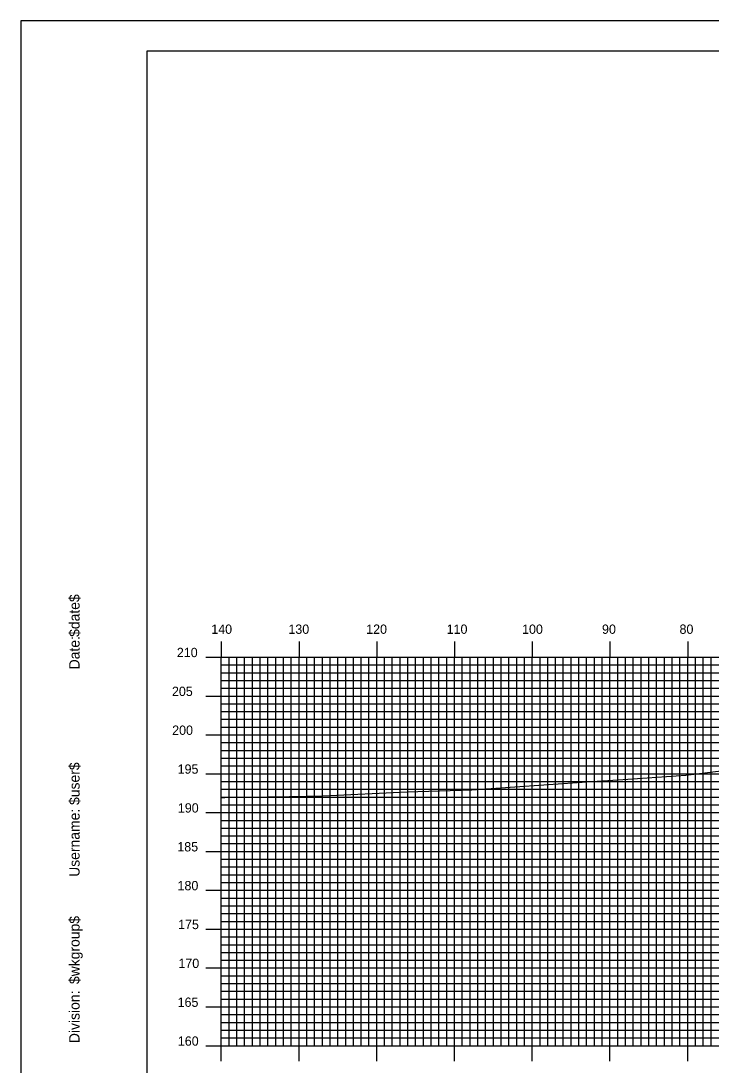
# Model space of a CAD drawing. Extents: x 1794846 to 1795189, y 442591 to 442811.
# Drawn here: x 1794846.1 to 1794934.9, y 442676.2 to 442810.5 of the extents above; entities that cross this region are included whole.
import ezdxf

# ---------------------------------------------------------------- set-up
doc = ezdxf.new("R2010")
doc.units = 0
for name, color, linetype in [('BORDER', 7, 'Continuous'), ('H_V ANNOTATION', 7, 'Continuous'), ('MAJOR', 7, 'Continuous'), ('MINOR', 7, 'Continuous'), ('PLOT BOUNDARY', 7, 'Continuous'), ('S_Roadway_Centerline', 7, 'Continuous')]:
    doc.layers.add(name, color=color, linetype=linetype)

msp = doc.modelspace()

# ---------------------------------------------------------------- linework, layer by layer
at = {"layer": 'BORDER'}
msp.add_lwpolyline([(1794862.25, 442596.67), (1795182.25, 442596.67), (1795182.25, 442806.67), (1794862.25, 442806.67)], close=True, dxfattribs=at)
at = {"layer": 'MAJOR'}
for p, q in [((1794871.85, 442730.67), (1794871.85, 442728.67)), ((1794881.85, 442730.67), (1794881.85, 442728.67)), ((1794891.85, 442730.67), (1794891.85, 442728.67)), ((1794901.85, 442730.67), (1794901.85, 442728.67)), ((1794911.85, 442730.67), (1794911.85, 442728.67)), ((1794921.85, 442730.67), (1794921.85, 442728.67)), ((1794931.85, 442730.67), (1794931.85, 442728.67)), ((1794869.85, 442728.67), (1794871.85, 442728.67)), ((1794871.85, 442728.67), (1795151.85, 442728.67)), ((1794871.85, 442678.67), (1794871.85, 442728.67)), ((1794871.85, 442678.67), (1794871.85, 442728.67)), ((1794871.85, 442728.67), (1795151.85, 442728.67)), ((1794881.85, 442678.67), (1794881.85, 442728.67)), ((1794891.85, 442678.67), (1794891.85, 442728.67)), ((1794901.85, 442678.67), (1794901.85, 442728.67)), ((1794911.85, 442678.67), (1794911.85, 442728.67)), ((1794921.85, 442678.67), (1794921.85, 442728.67)), ((1794931.85, 442678.67), (1794931.85, 442728.67)), ((1794869.85, 442723.67), (1794871.85, 442723.67)), ((1794871.85, 442723.67), (1795151.85, 442723.67)), ((1794869.85, 442718.67), (1794871.85, 442718.67)), ((1794871.85, 442718.67), (1795151.85, 442718.67)), ((1794869.85, 442713.67), (1794871.85, 442713.67)), ((1794871.85, 442713.67), (1795151.85, 442713.67)), ((1794869.85, 442708.67), (1794871.85, 442708.67)), ((1794871.85, 442708.67), (1795151.85, 442708.67)), ((1794869.85, 442703.67), (1794871.85, 442703.67)), ((1794871.85, 442703.67), (1795151.85, 442703.67)), ((1794869.85, 442698.67), (1794871.85, 442698.67)), ((1794871.85, 442698.67), (1795151.85, 442698.67)), ((1794869.85, 442693.67), (1794871.85, 442693.67)), ((1794871.85, 442693.67), (1795151.85, 442693.67)), ((1794869.85, 442688.67), (1794871.85, 442688.67)), ((1794871.85, 442688.67), (1795151.85, 442688.67)), ((1794869.85, 442683.67), (1794871.85, 442683.67)), ((1794871.85, 442683.67), (1795151.85, 442683.67)), ((1794869.85, 442678.67), (1794871.85, 442678.67)), ((1794871.85, 442678.67), (1795151.85, 442678.67)), ((1794871.85, 442678.67), (1795151.85, 442678.67)), ((1794871.85, 442676.66), (1794871.85, 442678.67)), ((1794881.85, 442676.66), (1794881.85, 442678.67)), ((1794891.85, 442676.66), (1794891.85, 442678.67)), ((1794901.85, 442676.66), (1794901.85, 442678.67)), ((1794911.85, 442676.66), (1794911.85, 442678.67)), ((1794921.85, 442676.66), (1794921.85, 442678.67)), ((1794931.85, 442676.66), (1794931.85, 442678.67))]:
    msp.add_line(p, q, dxfattribs=at)
at = {"layer": 'MINOR'}
for p, q in [((1794872.85, 442678.67), (1794872.85, 442728.67)), ((1794873.85, 442678.67), (1794873.85, 442728.67)), ((1794874.85, 442678.67), (1794874.85, 442728.67)), ((1794875.85, 442678.67), (1794875.85, 442728.67)), ((1794876.85, 442678.67), (1794876.85, 442728.67)), ((1794877.85, 442678.67), (1794877.85, 442728.67)), ((1794878.85, 442678.67), (1794878.85, 442728.67)), ((1794879.85, 442678.67), (1794879.85, 442728.67)), ((1794880.85, 442678.67), (1794880.85, 442728.67)), ((1794882.85, 442678.67), (1794882.85, 442728.67)), ((1794883.85, 442678.67), (1794883.85, 442728.67)), ((1794884.85, 442678.67), (1794884.85, 442728.67)), ((1794885.85, 442678.67), (1794885.85, 442728.67)), ((1794886.85, 442678.67), (1794886.85, 442728.67)), ((1794887.85, 442678.67), (1794887.85, 442728.67)), ((1794888.85, 442678.67), (1794888.85, 442728.67)), ((1794889.85, 442678.67), (1794889.85, 442728.67)), ((1794890.85, 442678.67), (1794890.85, 442728.67)), ((1794892.85, 442678.67), (1794892.85, 442728.67)), ((1794893.85, 442678.67), (1794893.85, 442728.67)), ((1794894.85, 442678.67), (1794894.85, 442728.67)), ((1794895.85, 442678.67), (1794895.85, 442728.67)), ((1794896.85, 442678.67), (1794896.85, 442728.67)), ((1794897.85, 442678.67), (1794897.85, 442728.67)), ((1794898.85, 442678.67), (1794898.85, 442728.67)), ((1794899.85, 442678.67), (1794899.85, 442728.67)), ((1794900.85, 442678.67), (1794900.85, 442728.67)), ((1794902.85, 442678.67), (1794902.85, 442728.67)), ((1794903.85, 442678.67), (1794903.85, 442728.67)), ((1794904.85, 442678.67), (1794904.85, 442728.67)), ((1794905.85, 442678.67), (1794905.85, 442728.67)), ((1794906.85, 442678.67), (1794906.85, 442728.67)), ((1794907.85, 442678.67), (1794907.85, 442728.67)), ((1794908.85, 442678.67), (1794908.85, 442728.67)), ((1794909.85, 442678.67), (1794909.85, 442728.67)), ((1794910.85, 442678.67), (1794910.85, 442728.67)), ((1794912.85, 442678.67), (1794912.85, 442728.67)), ((1794913.85, 442678.67), (1794913.85, 442728.67)), ((1794914.85, 442678.67), (1794914.85, 442728.67)), ((1794915.85, 442678.67), (1794915.85, 442728.67)), ((1794916.85, 442678.67), (1794916.85, 442728.67)), ((1794917.85, 442678.67), (1794917.85, 442728.67)), ((1794918.85, 442678.67), (1794918.85, 442728.67)), ((1794919.85, 442678.67), (1794919.85, 442728.67)), ((1794920.85, 442678.67), (1794920.85, 442728.67)), ((1794922.85, 442678.67), (1794922.85, 442728.67)), ((1794923.85, 442678.67), (1794923.85, 442728.67)), ((1794924.85, 442678.67), (1794924.85, 442728.67)), ((1794925.85, 442678.67), (1794925.85, 442728.67)), ((1794926.85, 442678.67), (1794926.85, 442728.67)), ((1794927.85, 442678.67), (1794927.85, 442728.67)), ((1794928.85, 442678.67), (1794928.85, 442728.67)), ((1794929.85, 442678.67), (1794929.85, 442728.67)), ((1794930.85, 442678.67), (1794930.85, 442728.67)), ((1794932.85, 442678.67), (1794932.85, 442728.67)), ((1794933.85, 442678.67), (1794933.85, 442728.67)), ((1794934.85, 442678.67), (1794934.85, 442728.67)), ((1794871.85, 442727.67), (1795151.85, 442727.67)), ((1794871.85, 442727.67), (1794873.86, 442727.67)), ((1794871.85, 442726.67), (1795151.85, 442726.67)), ((1794871.85, 442726.67), (1794873.86, 442726.67)), ((1794871.85, 442725.67), (1795151.85, 442725.67)), ((1794871.85, 442725.67), (1794873.86, 442725.67)), ((1794871.85, 442724.67), (1795151.85, 442724.67)), ((1794871.85, 442724.67), (1794873.86, 442724.67)), ((1794871.85, 442722.67), (1795151.85, 442722.67)), ((1794871.85, 442722.67), (1794873.86, 442722.67)), ((1794871.85, 442721.67), (1795151.85, 442721.67)), ((1794871.85, 442721.67), (1794873.86, 442721.67)), ((1794871.85, 442720.67), (1795151.85, 442720.67)), ((1794871.85, 442720.67), (1794873.86, 442720.67)), ((1794871.85, 442719.67), (1795151.85, 442719.67)), ((1794871.85, 442719.67), (1794873.86, 442719.67)), ((1794871.85, 442717.67), (1795151.85, 442717.67)), ((1794871.85, 442717.67), (1794873.86, 442717.67)), ((1794871.85, 442716.67), (1795151.85, 442716.67)), ((1794871.85, 442716.67), (1794873.86, 442716.67)), ((1794871.85, 442715.67), (1795151.85, 442715.67)), ((1794871.85, 442715.67), (1794873.86, 442715.67)), ((1794871.85, 442714.67), (1795151.85, 442714.67)), ((1794871.85, 442714.67), (1794873.86, 442714.67)), ((1794871.85, 442712.67), (1795151.85, 442712.67)), ((1794871.85, 442712.67), (1794873.86, 442712.67)), ((1794871.85, 442711.67), (1795151.85, 442711.67)), ((1794871.85, 442711.67), (1794873.86, 442711.67)), ((1794871.85, 442710.67), (1795151.85, 442710.67)), ((1794871.85, 442710.67), (1794873.86, 442710.67)), ((1794871.85, 442709.67), (1795151.85, 442709.67)), ((1794871.85, 442709.67), (1794873.86, 442709.67)), ((1794871.85, 442707.67), (1795151.85, 442707.67)), ((1794871.85, 442707.67), (1794873.86, 442707.67)), ((1794871.85, 442706.67), (1795151.85, 442706.67)), ((1794871.85, 442706.67), (1794873.86, 442706.67)), ((1794871.85, 442705.67), (1795151.85, 442705.67)), ((1794871.85, 442705.67), (1794873.86, 442705.67)), ((1794871.85, 442704.67), (1795151.85, 442704.67)), ((1794871.85, 442704.67), (1794873.86, 442704.67)), ((1794871.85, 442702.67), (1795151.85, 442702.67)), ((1794871.85, 442702.67), (1794873.86, 442702.67)), ((1794871.85, 442701.67), (1795151.85, 442701.67)), ((1794871.85, 442701.67), (1794873.86, 442701.67)), ((1794871.85, 442700.67), (1795151.85, 442700.67)), ((1794871.85, 442700.67), (1794873.86, 442700.67)), ((1794871.85, 442699.67), (1795151.85, 442699.67)), ((1794871.85, 442699.67), (1794873.86, 442699.67)), ((1794871.85, 442697.67), (1795151.85, 442697.67)), ((1794871.85, 442697.67), (1794873.86, 442697.67)), ((1794871.85, 442696.67), (1795151.85, 442696.67)), ((1794871.85, 442696.67), (1794873.86, 442696.67)), ((1794871.85, 442695.67), (1795151.85, 442695.67)), ((1794871.85, 442695.67), (1794873.86, 442695.67)), ((1794871.85, 442694.67), (1795151.85, 442694.67)), ((1794871.85, 442694.67), (1794873.86, 442694.67)), ((1794871.85, 442692.67), (1795151.85, 442692.67)), ((1794871.85, 442692.67), (1794873.86, 442692.67)), ((1794871.85, 442691.67), (1795151.85, 442691.67)), ((1794871.85, 442691.67), (1794873.86, 442691.67)), ((1794871.85, 442690.67), (1795151.85, 442690.67)), ((1794871.85, 442690.67), (1794873.86, 442690.67)), ((1794871.85, 442689.67), (1795151.85, 442689.67)), ((1794871.85, 442689.67), (1794873.86, 442689.67)), ((1794871.85, 442687.67), (1795151.85, 442687.67)), ((1794871.85, 442687.67), (1794873.86, 442687.67)), ((1794871.85, 442686.67), (1795151.85, 442686.67)), ((1794871.85, 442686.67), (1794873.86, 442686.67)), ((1794871.85, 442685.67), (1795151.85, 442685.67)), ((1794871.85, 442685.67), (1794873.86, 442685.67)), ((1794871.85, 442684.67), (1795151.85, 442684.67)), ((1794871.85, 442684.67), (1794873.86, 442684.67)), ((1794871.85, 442682.67), (1795151.85, 442682.67)), ((1794871.85, 442682.67), (1794873.86, 442682.67)), ((1794871.85, 442681.67), (1795151.85, 442681.67)), ((1794871.85, 442681.67), (1794873.86, 442681.67)), ((1794871.85, 442680.67), (1795151.85, 442680.67)), ((1794871.85, 442680.67), (1794873.86, 442680.67)), ((1794871.85, 442679.67), (1795151.85, 442679.67)), ((1794871.85, 442679.67), (1794873.86, 442679.67))]:
    msp.add_line(p, q, dxfattribs=at)
at = {"layer": 'PLOT BOUNDARY'}
msp.add_lwpolyline([(1794846.07, 442590.55), (1795186.07, 442590.55), (1795186.07, 442810.55), (1794846.07, 442810.55)], close=True, dxfattribs=at)
at = {"layer": 'S_Roadway_Centerline'}
msp.add_lwpolyline([(1794871.85, 442710.63), (1794872.31, 442710.63), (1794880.62, 442710.75), (1794884.89, 442710.84), (1794895.77, 442711.36), (1794904.1, 442711.61), (1794918.86, 442712.61), (1794922.9, 442712.89), (1794931.62, 442713.49), (1794942.42, 442714.81)], dxfattribs=at)

# ---------------------------------------------------------------- texts
at = {"layer": 'BORDER'}
for s, p in [('$date$', (1794853.62, 442731.28)), ('Date:', (1794853.62, 442727.1)), ('$user$', (1794853.62, 442709.65)), ('Username:', (1794853.62, 442700.4)), ('$wkgroup$', (1794853.62, 442686.6)), ('Division:', (1794853.62, 442679))]:
    msp.add_text(s, height=1.339, rotation=90, dxfattribs=at).set_placement(p)
at = {"layer": 'H_V ANNOTATION'}
for s, p in [('140', (1794870.56, 442731.67)), ('130', (1794880.48, 442731.67)), ('120', (1794890.49, 442731.67)), ('110', (1794900.84, 442731.67)), ('100', (1794910.54, 442731.67)), ('90', (1794920.83, 442731.67)), ('80', (1794930.8, 442731.67)), ('210', (1794866.13, 442728.67)), ('205', (1794865.5, 442723.67)), ('200', (1794865.53, 442718.67)), ('195', (1794866.23, 442713.67)), ('190', (1794866.26, 442708.67)), ('185', (1794866.19, 442703.67)), ('180', (1794866.22, 442698.67)), ('175', (1794866.29, 442693.67)), ('170', (1794866.33, 442688.67)), ('165', (1794866.23, 442683.67)), ('160', (1794866.26, 442678.67))]:
    msp.add_text(s, height=1.2, dxfattribs=at).set_placement(p)
at = {"layer": 'MAJOR'}
msp.add_text('-', height=0.012, dxfattribs=at).set_placement((1794871.84, 442678.67))

doc.saveas('drawing.dxf')
